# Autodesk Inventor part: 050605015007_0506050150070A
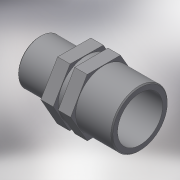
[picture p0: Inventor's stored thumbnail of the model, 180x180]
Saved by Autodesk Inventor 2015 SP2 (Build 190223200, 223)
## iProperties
Created: 2017-05
Part Number: 050605015007_0506050150070A
Material: Generic
Description: PLASSON REDUCING NIPPLE 1.1/2"-3/4"
Document SubType Name: Modeling
Designer: KIM
Density: 1 g/cm^3
Appearance: Default
Author: KIM
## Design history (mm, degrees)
derived "050605.ipt"
feature "Solid1::050605.ipt"
tag "TaggingFeature1"
body "Solid1"
other parameters: "d0" = 55, "d1" = 47.803, "d5" = 21, "d6" = 5.5, "d8" = 0.55, "d12" = 0, "d14" = 26.441, "d15" = 21.1528, "d16" = 38.2424, "d17" = 17, "d18" = 2.75, "d21" = 0, "H_" = 55, "R_" = 47.803, "l_" = 21, "R_1" = 26.441, "l_1" = 17
